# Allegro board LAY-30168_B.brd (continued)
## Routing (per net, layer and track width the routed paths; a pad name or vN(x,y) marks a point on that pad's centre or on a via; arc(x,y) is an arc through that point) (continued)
JTAG_MOD: length 13.2
  TOP w0.127: TP11.1 74.12,56.9 R303.1 72,56.52 71.88,56.39 66.22,56.39 65.96,56.13 63.44,56.13 63.21,55.9 62.31,55.9 U1.F13
JTAG_NSRST: length 9.5
  TOP w0.127: D13.C R175.2 28.07,88.27 28.21,88.41 28.21,94.01 J21.15
JTAG_RESET: length 16.2
  TOP w0.127: v2(131.61,77.37) 130,77.37 U38.D10 ; J44.2 136.78,84.45 v2(136.78,77.37)
  BOTTOM w0.127: v2(136.78,77.37) v2(131.61,77.37)
JTAG_RTCK: length 9
  TOP w0.127: R181.1 32.02,88.01 33.29,89.28 33.29,94.01 J21.11
JTAG_TCK: length 165.5
  TOP w0.127: v2(104.14,77.47) 104.14,75.44 104.9,74.68 104.9,58.34 102.97,56.4 86.43,56.4 85.02,57.81 66.19,57.81 65.28,56.9 63.37,56.9 63.01,56.54 61.66,56.54 U1.F12 ; J21.9 35.81,94.02 35.81,89.27 v2(34.56,88.01) R180.1
  BOTTOM w0.127: v2(104.14,77.47) 103.5,78.11 103.5,90.55 104.27,91.31 J48.2 102.23,92.33 90.81,92.33 89.41,93.73 52.4,93.73 47.7,89.03 40.26,89.03 38.61,87.38 35.19,87.38 v2(34.56,88.01)
JTAG_TDI_L: length 45.8
  TOP w0.127: U48.3 96.26,90.81 96.65,90.42 110.19,90.42 111.46,89.15 122.95,89.15 126.05,86.05 128.97,86.05 133.61,81.41 U38.J10
JTAG_TDI_TGTMCU_BUF: length 4.4
  TOP w0.127: R417.2 97.92,97.41 98.42,96.9 J49.1
JTAG_TDO_TGTMCU_BUF: length 11.2
  TOP w0.127: U49.4 93.97,88.03 93.34,88.65 92.72,88.65 R422.1 92.71,95.5 J50.1
JTAG_TMS: length 166.3
  TOP w0.127: R176.2 v2(37.1,88.01) 38.37,89.28 38.37,94.01 J21.7 ; v2(104.12,78.72) 103.63,78.23 103.63,75.18 104.52,74.3 104.52,58.49 102.81,56.78 86.59,56.78 85.13,58.24 65.89,58.24 64.86,57.22 62.99,57.22 U1.E14
  BOTTOM w0.127: v2(37.1,88.01) 38.5,89.41 47.54,89.41 52.37,94.23 89.53,94.23 90.93,92.84 100.84,92.84 103.5,95.5 106.81,95.5 J47.2 104.12,90.53 v2(104.12,78.72)
JTAG_VREF: length 8.9
  TOP w0.127: J21.1 45.97,94.02 45.97,88.62 R179.2
LCD_3V3: length 68
  TOP w0.305: v2(90.04,73.79) 90.04,72.14 89.15,71.25 88.14,71.25 87.66,71.73 85.57,71.73 84.79,72.52 81.86,72.52 79.46,74.92 v2(78.87,74.92) 76.6,74.92 70,68.33 v2(55.12,68.33)
  BOTTOM w0.305: J8.B1 C92.1
  BOTTOM w0.381: v2(55.12,68.33) 55.12,68.96 49.78,74.3 37.46,74.3 36.83,73.66 C92.1 ; R67.1 v2(78.87,74.92)
LCDIF_CLK: length 31
  TOP w0.127: v2(68.07,65.79) 68.07,66.55 68.58,67.06 74.17,67.06 76.83,69.72 78.49,69.72 v2(78.99,69.22) ; U1.D7 v1(57.77,57.84)
  BOTTOM w0.102: v1(57.77,57.84) 57.77,58.04 58.16,58.43 58.16,60.17
  BOTTOM w0.127: J8.A30 80.15,69.48 79.88,69.22 v2(78.99,69.22) ; v2(68.07,65.79) 67.58,65.29 62.71,65.29 58.16,60.75 58.16,60.17
LCDIF_D12: length 37.7
  TOP w0.127: U1.A11 60.7,60.2 60.9,60.4 60.9,60.52 63.25,62.87 78.52,62.87 80.28,64.63 89.3,64.63 89.92,65.25 89.92,68.76 v2(90.5,69.34)
  BOTTOM w0.127: J8.A9 90.65,69.49 v2(90.5,69.34)
LCDIF_D13: length 38.5
  TOP w0.127: v2(90.42,67.31) 90.42,65.12 89.56,64.26 80.44,64.26 78.67,62.5 63.39,62.5 61.03,60.14 61.03,59.15 U1.B11
  BOTTOM w0.127: J8.A10 90.15,69.83 90.03,69.71 90.03,67.7 v2(90.42,67.31)
LCDIF_D14: length 37.7
  TOP w0.127: U1.C11 v1(61.02,58.49)
  BOTTOM w0.102: v1(61.02,58.49) 61.02,58.7 61.5,59.18 63.12,59.18
  BOTTOM w0.127: J8.A11 89.65,64.5 88.14,62.99 85.47,62.99 83.79,61.32 65.25,61.32 63.12,59.18
LCDIF_D15: length 38.6
  TOP w0.127: U1.D11 v1(61.02,57.84)
  BOTTOM w0.102: 62.03,60.58 61.14,59.7 61.14,59.11 60.7,58.66 60.7,58.18 61.02,57.85 v1(61.02,57.84)
  BOTTOM w0.127: 62.03,60.58 63.09,61.65 83.42,61.65 85.07,63.3 87.93,63.3 89.15,64.51 J8.A12
LCDIF_ENABLE: length 28.7
  TOP w0.127: v2(69.22,65.79) 74.72,65.79 v2(78.15,69.22) ; U1.E7 v1(57.77,57.19)
  BOTTOM w0.102: v1(57.77,57.19) 58.09,57.52 58.09,58 58.42,58.33 58.42,60.46 58.54,60.58
  BOTTOM w0.127: 58.54,60.58 58.54,60.59 62.87,64.91 68.34,64.91 v2(69.22,65.79) ; J8.A34 v2(78.15,69.22)
LCDIF_HSYNC: length 32.5
  TOP w0.127: U1.E8 v1(59.07,57.19)
  BOTTOM w0.102: 58.96,60.58 58.75,60.36 58.75,57.52 v1(59.07,57.19)
  BOTTOM w0.127: J8.A32 79.15,71.6 78.49,72.26 73.15,72.26 70.61,69.72 70.61,66.29 68.83,64.52 62.9,64.52 58.96,60.58
LCDIF_VSYNC: length 30.8
  TOP w0.127: U1.D8 v1(59.07,57.84)
  BOTTOM w0.102: 59.39,60.58 58.99,60.17 58.99,57.93 v1(59.07,57.84)
  BOTTOM w0.127: 59.39,60.58 62.82,64.01 69.14,64.01 70.92,65.79 70.92,69.6 73.28,71.96 78.28,71.96 78.65,71.59 J8.A33
LDO_1V8: length 96.1
  BOTTOM w0.381: v2(49.02,9.91) v2(49.02,9.14) 53.37,4.8 69.62,4.8 71.12,3.3 75.69,3.3 78.87,6.48 90.55,6.48 91.31,5.71 93.22,5.71 102.36,14.86 116.33,14.86 126.11,5.08 L20.1
MAIN_MIC2N: length 3.2
  TOP w0.254: U13.5 127.38,29.09 C130.1 C126.2
MAIN_MIC2P: length 4.1
  TOP w0.254: U13.6 126.88,28.44 126.52,28.8 125.89,28.8 C118.2 124.34,29.47 C122.2
MCU_DCDC_IN: length 6.1
  TOP w0.254: U1.K4 v1(55.82,53.3) ; v1(52.83,52.6) 53.06,52.83 v1(53.31,52.83) 53.45,52.97 U1.L1 v1(54.52,52.64) U1.L2
  INT1 w0.102: 54.1,53.34 54.38,53.62 55.5,53.62 v1(55.82,53.3) 55.5,52.97 54.75,52.97
  vias: v2(43.43,46.99) v2(43.43,46.35)
MICBIAS: length 22.9
  TOP w0.254: U13.1 129.39,27.76 129.69,28.07 130.3,28.07
  TOP w0.305: R104.1 v2(127.89,34.92) ; v2(132.33,29.47) C112.1 131.57,29.34 130.3,28.07
  TOP w0.381: R105.1 v2(122.68,32.01)
  BOTTOM w0.305: v2(132.33,29.47) 128.9,29.47 127.89,30.48 v2(127.89,34.92) 123.11,34.92 122.68,34.49 v2(122.68,32.01)
NVCC_SD: length 15.2
  TOP w0.305: v2(48.64,50.16) 48.64,51.3 R60.1
  BOTTOM w0.305: v2(48.64,50.16) 46.02,47.55 42.85,47.55 40.51,45.21 v2(40.51,41.66)
ONOFF: length 69
  TOP w0.127: U1.M6 57.13,52 57.13,50.65 56.87,50.39 56.87,47.85 56.38,47.36 56.38,45.91 56.81,45.48 56.81,44.31 57.14,43.98 58.25,43.98 60.33,41.91 60.33,38.48 59.44,37.59 59.44,37.08 59.65,36.87 62.32,36.87 65.15,34.04 65.91,34.04 67.82,32.13 67.82,25.53 60.45,18.16 60.45,7.96 59.82,7.33 SW2.3 SW2.4
OTG1_DN: length 64.6
  TOP w0.102: v1(58.42,52.64) 58.74,52.32 U1.M8
  TOP w0.119: v2(61.14,46.49) 60.87,46.76 60.72,46.76 60.58,46.62 60.58,43.56 61.85,42.29 61.85,40.51 65.29,37.08 74.02,37.08 79.88,31.21 79.88,22.23 81.79,20.32 83.69,20.32 85.85,18.16 89.63,18.16 91.05,16.74 91.05,13.6 91.33,13.32 L5.2 R68.2
  BOTTOM w0.102: v1(58.42,52.64) 58.61,52.83 58.7,52.83 58.8,52.73 58.8,51.11 58.89,51.02 58.89,50.91 58.89,50.91 58.89,50.89
  BOTTOM w0.119: v2(61.14,46.49) 60.68,46.95 60.68,47.25 60.04,47.89 60.04,48.4 58.89,49.55 58.89,50.89
OTG1_DP: length 64.6
  TOP w0.102: v1(58.42,53.29) 58.74,52.97 U1.L8
  TOP w0.119: v2(61.14,47.34) 60.81,47.01 60.61,47.01 60.33,46.73 60.33,43.46 61.6,42.19 61.6,40.41 65.18,36.83 73.91,36.83 79.64,31.11 79.64,22.12 81.69,20.07 83.59,20.07 85.75,17.91 89.53,17.91 90.8,16.64 90.8,13.59 90.53,13.31 L5.3 R69.2
  BOTTOM w0.102: v1(58.42,53.29) 58.65,53.06 58.79,53.06 59.03,52.83 59.03,51.21 59.13,51.11 59.13,50.9
  BOTTOM w0.119: v2(61.14,47.34) 60.94,47.34 60.29,47.99 60.29,48.5 59.14,49.65 59.14,50.89 59.13,50.9
OTG2_DN: length 53.9
  TOP w0.102: 58.46,49.89 58.46,49.92 58.43,49.95 58.43,51.34 U1.N7
  TOP w0.119: 58.46,49.89 58.46,44.74 60.96,42.24 60.96,40.26 64.9,36.32 73.41,36.32 78.74,30.99 78.74,21.97 80.38,20.33 80.38,13.65 80.66,13.37 L8.2 R83.2
OTG2_DP: length 53.8
  TOP w0.102: 58.22,49.89 58.22,49.92 58.23,49.93 58.23,50.89 U1.P7
  TOP w0.119: R84.2 L8.3 79.86,13.36 80.13,13.63 80.13,13.94 80.01,14.06 79.93,14.06 79.81,14.18 79.81,14.42 79.93,14.53 80.01,14.53 80.13,14.65 80.13,14.89 80.01,15.01 79.93,15.01 79.81,15.13 79.81,15.37 79.93,15.49 80.01,15.49 80.13,15.61 80.13,20.23 78.49,21.87 78.49,30.89 73.3,36.08 64.79,36.08 60.71,40.16 60.71,42.14 58.22,44.63 58.22,49.89
PERI_3V3:
  vias: v2(89.92,75.69) v2(89.92,75.06) v2(90.68,75.69)
PERI_PWREN: length 121.2
  TOP w0.127: v2(91.82,79.76) 104.29,79.76 105.79,78.26 105.79,73.66 106.6,72.85 106.6,58.09 103.54,55.03 84.75,55.03 83.86,54.14 79.43,54.14 v2(78.74,53.45) ; U1.L7 v1(57.77,52.65) ; Q6.1 88.38,76.51 v2(88.77,76.91) R31.1
  BOTTOM w0.102: 58.09,50.9 58.09,52.32 v1(57.77,52.65)
  BOTTOM w0.127: v2(78.74,53.45) 78.74,52.7 77.34,51.31 76.71,51.31 75.31,49.91 75.31,37.08 73.03,34.8 71.12,34.8 69.85,36.07 69.85,39.37 68.58,40.64 65.56,40.64 60.34,45.86 60.34,47.16 58.45,49.05 58.45,50.55 58.09,50.9 ; v2(91.82,79.76) 91.62,79.76 v2(88.77,76.91)
PMIC_ON_REQ: length 65
  TOP w0.127: U1.K7 v1(57.77,53.3) ; v2(63.12,33.78) 62.48,33.15 50.8,33.15 v2(50.04,32.38) ; v2(44.32,17.27) 44.82,16.77 R355.1 ; v2(36.96,20.95) R38.2
  BOTTOM w0.102: v1(57.77,53.3) 57.77,53.1 57.44,52.78 57.44,50.24 57.61,50.07 57.61,49.91
  BOTTOM w0.127: v2(50.04,32.38) 50.04,29.84 44.96,24.77 44.96,17.91 v2(44.32,17.27) 43.69,17.91 38.73,17.91 36.96,19.68 v2(36.96,20.95) ; v2(63.12,33.78) 62.61,34.29 62.61,40.51 58.83,44.3 58.83,45.79 58.55,46.06 58.55,46.79 57.61,47.73 57.61,49.91
POR_B: length 242.6
  TOP w0.203: U44.7 143.26,87.25 R401.2 141.61,86.61 R410.2 139.96,86.48 138.68,87.76 134.75,87.76 J43.3
  TOP w0.254: U1.M7 v1(57.77,52)
  TOP w0.305: v2(32.64,43.18) D7.C 31.08,43.94 27.69,43.94 26.29,42.55 J26.1 25.4,70.1 22.1,73.41 22.1,82.42 25.44,85.76 D13.A v2(27.85,85.76) ; J43.3 129.93,89.53 D21.C 128.74,90.22 124.16,90.22 123.8,90.58 114.4,90.58 114.05,90.93 113.16,90.93 v2(113.03,91.06) ; R20.2 C27.1 61.62,43.18 v2(61.11,43.69) ; v2(63.12,34.67) v2(47.75,34.67)
  BOTTOM w0.254: v1(57.77,52) 57.77,50.48 58.04,50.22 58.04,47.85
  BOTTOM w0.305: 58.04,47.85 59.06,46.83 R21.2 59.06,46.11 59.24,45.93 59.24,44.65 59.87,44.02 60.78,44.02 v2(61.11,43.69) 63.12,41.68 v2(63.12,34.67) ; v2(47.75,34.67) 46.56,35.86 44.91,35.86 37.59,43.18 v2(32.64,43.18) ; v2(27.85,85.76) 32.26,90.17 46.91,90.17 51.59,94.84 85.45,94.84 88.77,98.17 109.6,98.17 113.03,94.74 v2(113.03,91.06)
POR_BUTTON: length 20.4
  TOP w0.127: R355.2 R43.1 43.3,15.63 44.32,14.6 44.32,8.13 43.52,7.33 SW3.3 SW3.4
POWER_EN: length 16.8
  TOP w0.305: U38.F7 v2(131.61,75.77) ; R216.1 v2(126.49,63.25)
  BOTTOM w0.305: v2(131.61,75.77) 132.72,74.66 132.72,70.1 126.49,63.88 v2(126.49,63.25)
PWDN: length 7.5
  TOP w0.254: J35.17 134.96,8.85 135.64,9.53 136.02,9.53 136.4,9.91 R219.2 136.14,10.55 135.83,10.86 D17.A
SD0_VSELECT: length 120.6
  TOP w0.254: U1.C14 63.89,58.17 65.05,59.33 v2(85.09,59.33) ; Q9.2 41.38,37.1 41.18,37.29 41.18,37.83 41.45,38.1 R54.1 42.55,36.32 43.43,35.43 63.11,35.43 65.4,33.15 65.96,33.15 67.18,31.93 v2(67.18,29.21) ; v2(96.14,32) v2(85.34,32)
  BOTTOM w0.254: v2(85.09,59.33) 85.09,58.8 86.61,57.28 89.11,57.28 96.9,49.48 96.9,32.77 v2(96.14,32) ; v2(85.34,32) 82.68,32 79.88,29.21 v2(67.18,29.21)
SD1_CLK: length 19.1
  TOP w0.127: U1.J3 v1(55.17,53.95)
  BOTTOM w0.102: v1(55.17,53.95) 54.64,53.95 54.61,53.98 53.09,53.98 52.32,53.21
  BOTTOM w0.127: R282.1 39.74,48.39 C244.1 41.52,48.38 42.1,48.96 45.48,48.96 48.76,52.25 49.58,52.25 50.16,52.83 51.27,52.83 51.66,53.21 52.32,53.21
SD1_D2: length 54.1
  TOP w0.127: TP27.1 49.4,53.09 v2(49.4,53.34) 49.78,53.34 50.67,54.23 53.38,54.23 53.76,54.6 54.53,54.6 U1.H2 ; v2(19.94,51.69) 19.03,50.78 J39.1
  BOTTOM w0.127: v2(49.4,53.34) 48.92,52.86 48.46,52.86 45.17,49.57 41.53,49.57 41.36,49.4 28.02,49.4 26.37,51.05 25.28,51.05 25.15,51.18 25.15,51.56 25.03,51.69 24.77,51.69 24.65,51.56 24.65,51.18 24.52,51.05 24.18,51.05 24.06,51.18 24.06,52.2 23.93,52.32 23.68,52.32 23.55,52.2 23.55,51.18 23.42,51.05 23.17,51.05 23.04,51.18 23.04,52.2 22.91,52.32 22.66,52.32 22.53,52.2 22.53,51.18 22.41,51.05 22.15,51.05 22.02,51.18 22.02,52.2 21.9,52.32 21.64,52.32 21.52,52.2 21.52,51.82 21.39,51.69 v2(19.94,51.69)
SD1_D3: length 54.8
  TOP w0.127: U1.J2 54.52,53.95 53.89,53.95 53.55,53.61 52.21,53.61 51.94,53.34 v2(51.05,53.34) 50.87,53.15 50.87,51.63 TP28.1 ; v2(17.65,52.7) 16.83,51.88 J39.2
  BOTTOM w0.127: v2(17.65,52.7) R172.1 18.42,52.06 19.56,50.93 21.08,50.93 22.1,49.91 22.1,49.52 22.23,49.39 22.48,49.39 22.61,49.52 22.61,50.29 22.74,50.42 22.99,50.42 23.12,50.29 23.12,49.52 23.25,49.39 23.5,49.39 23.63,49.52 23.63,50.24 23.75,50.37 24.01,50.37 24.13,50.24 24.13,49.52 24.26,49.39 24.52,49.39 24.64,49.52 24.64,50.19 24.77,50.32 25.02,50.32 25.15,50.19 25.15,49.52 25.28,49.39 25.53,49.39 25.66,49.52 25.66,50.06 25.79,50.19 26.14,50.19 27.36,48.97 41.49,48.97 41.78,49.26 45.32,49.26 48.61,52.55 49.38,52.55 50.17,53.34 51.05,53.34 v2(51.05,53.34)
SD_CD_SW: length 151.7
  TOP w0.127: v2(27.94,57.78) 27.94,63.25 31.88,67.18 52.95,67.18 54.61,68.85 68.59,68.85 77.69,77.94 99.81,77.94 103.89,73.86 103.89,58.72 102.56,57.39 86.84,57.39 85.38,58.85 65.46,58.85 64.44,57.84 62.51,57.84 62.2,57.52 U1.D13
  BOTTOM w0.127: R320.2 24.5,57.78 24.51,57.78 v2(27.94,57.78)
SDA_JTAG_TCLK: length 24.2
  TOP w0.127: U38.H2 133.2,71.76 133.2,74.74 132.99,74.96 131.03,74.96 130.81,75.18 130.81,76.43 130.68,76.56 129.41,76.56 129.2,76.77 129.2,77.13 128.97,77.36 128.61,77.36 128.4,77.57 128.4,77.93 126.32,80.01 124.59,80.01 123.19,81.41 121.92,81.41 120.27,83.06 120.27,83.69 J34.4
SDA_JTAG_TDI: length 20.6
  TOP w0.127: J34.8 121.79,79.63 121.79,77.22 122.3,76.71 124.59,76.71 125.73,75.56 126.75,75.56 126.96,75.77 127.43,75.77 127.62,75.58 127.62,75.2 127.85,74.97 128.96,74.97 129.2,74.73 129.2,74.42 129.45,74.17 130.68,74.17 130.82,74.03 130.82,73.6 131.05,73.37 131.48,73.37 131.6,73.25 131.6,72.57 U38.G3
SDA_JTAG_TDO: length 21.9
  TOP w0.127: U38.H3 132.42,72.56 132.42,73.92 132.16,74.17 131.05,74.17 130.82,74.4 130.82,74.72 130.56,74.97 130.23,74.97 130.02,75.19 130.02,75.55 129.79,75.77 127.85,75.77 127.6,76.02 127.6,76.33 127.37,76.56 126.51,76.56 125.35,77.72 122.81,77.72 122.17,78.36 122.17,80.52 J34.6
SDA_JTAG_TMS: length 24.1
  TOP w0.127: J34.2 120.91,84.32 R213.2 v2(120.91,83.19) ; U38.C4 128.4,72.56 125.65,72.56 124.46,71.37 122.3,71.37 121.92,71.75 121.92,73.41 120.9,74.42 v2(120.9,78.36)
  BOTTOM w0.127: v2(120.91,83.19) 120.9,83.18 v2(120.9,78.36)
SDA_RST: length 16
  TOP w0.127: U38.B4 127.61,73.37 124.42,73.37 R423.2 123.39,73.46 122.5,73.46 121.41,74.55 121.41,78.74 J34.10
SDA_RST_LED: length 1.6
  TOP w0.127: R412.2 128.13,88.28 D21.A
SDA_RST_TGTMCU_J_B: length 15.1
  TOP w0.127: J44.1 141.47,85.72 R410.1 142.25,84.96 145.92,84.96 147.32,86.36 147.32,90.04 R400.1
SDA_USB_CONN_DM: length 11.7
  TOP w0.119: J41.2 145.32,72.24 145.13,72.42 144.78,72.42 U39.2 143.86,72.26 143.74,72.38 143.47,72.38 143.25,72.16 143.25,70.86 140.62,68.23 138.35,68.23 R375.1
SDA_USB_CONN_DP: length 11.7
  TOP w0.119: R376.1 138.35,68.47 140.52,68.47 143,70.96 143,72.26 143.37,72.63 143.74,72.63 143.86,72.75 U39.3 144.68,72.69 145.16,72.69 145.35,72.89 J41.3
SDA_USB_DM: length 9.7
  TOP w0.119: U38.E2 130.41,71.23 130.02,70.84 130.02,69.91 131.7,68.23 136.96,68.23 R375.2
SDA_USB_DP: length 8.4
  TOP w0.119: R376.2 136.96,68.47 131.81,68.47 130.27,70.01 130.27,70.45 130.39,70.57 U38.E1
SDRAM_3V3: length 12.2
  TOP w0.254: U20.B3 v2(36.45,58.99) 36.51,58.93 37.72,58.93 ; U20.J9 v2(30.06,54.19) ; U20.E7 v2(34.06,55.79) ; U20.A9 37.25,54.19 37.93,54.19 38.1,54.36 C169.1 ; U20.A7 v2(37.25,56.59) 37.71,56.13 C167.1 ; U20.D3 v2(34.85,59.78) ; U20.C7 v2(35.65,56.59)
  TOP w0.305: C165.1 38.1,59.31 37.72,58.93 ; C169.1 C167.1
SEMC_A0: length 34.4
  TOP w0.127: U1.C2 54.53,58.49 53.21,58.49 52.14,59.56 45.12,59.56 44.97,59.41 44.97,58.7 44.82,58.55 44.61,58.55 44.46,58.7 44.46,59.41 44.31,59.56 44.1,59.56 43.95,59.41 43.95,58.7 43.8,58.55 43.59,58.55 43.44,58.7 43.44,59.41 43.3,59.56 43.09,59.56 42.94,59.41 42.94,58.7 42.79,58.55 42.58,58.55 42.43,58.7 42.43,59.41 42.28,59.56 42.07,59.56 41.92,59.41 41.92,58.7 41.77,58.55 41.56,58.55 41.41,58.7 41.41,59.41 41.26,59.56 41.02,59.56 40.89,59.44 40.89,58.04 40.26,57.4 30.99,57.4 30.73,57.15 30.73,56.71 U20.H7
SEMC_A1: length 34.6
  TOP w0.127: U20.H8 30.86,54.99 30.86,54.02 30.73,53.89 30.53,53.89 30.4,53.77 30.4,53.51 30.53,53.38 30.73,53.38 30.86,53.26 30.86,52.76 30.07,51.97 30.07,51.56 31.06,50.58 31.24,50.58 31.5,50.84 31.68,50.84 31.86,50.66 31.86,50.48 31.6,50.22 31.6,50.04 31.78,49.86 31.96,49.86 32.22,50.12 32.4,50.12 32.58,49.95 32.58,49.77 32.31,49.5 32.31,49.32 32.49,49.15 42.39,49.15 48.55,55.31 52.79,55.31 53.06,55.57 U1.G1
SEMC_A2: length 34.7
  TOP w0.127: U20.J8 29.64,54.57 29.64,53.34 29.77,53.21 29.97,53.21 30.1,53.08 30.1,52.83 29.97,52.7 29.77,52.7 29.64,52.57 29.64,51.36 32.23,48.77 42.49,48.77 48.65,54.93 52.95,54.93 53.26,55.24 55.17,55.24 U1.G3
SEMC_A3: length 34.3
  TOP w0.127: U20.J7 29.31,55.04 29.31,50.98 31.9,48.39 42.62,48.39 48.78,54.55 53.21,54.55 53.58,54.92 U1.H1
SEMC_A4: length 36.7
  TOP w0.127: U20.J3 29.34,60.5 29.34,62.61 32.51,65.79 52.83,65.79 57.44,61.17 U1.A6
SEMC_A5: length 35.3
  TOP w0.127: U1.B6 57.13,59.14 57.13,60.86 52.58,65.41 32.64,65.41 29.67,62.43 29.67,60.97 U20.J2
SEMC_A6: length 34.8
  TOP w0.127: U1.B1 53.32,58.82 52.96,59.18 52.96,59.82 52.83,59.94 52.61,59.94 52.46,60.09 52.46,60.56 52.31,60.71 52.1,60.71 51.96,60.56 51.96,60.09 51.81,59.94 51.6,59.94 51.45,60.09 51.45,60.56 51.3,60.71 51.09,60.71 50.94,60.56 50.94,60.09 50.79,59.94 50.58,59.94 50.43,60.09 50.43,60.56 50.28,60.71 50.07,60.71 49.92,60.56 49.92,60.09 49.77,59.94 49.56,59.94 49.42,60.09 49.42,60.56 49.27,60.71 49.06,60.71 48.91,60.56 48.91,60.09 48.76,59.94 48.55,59.94 48.4,60.09 48.4,60.56 48.25,60.71 48.04,60.71 47.89,60.56 47.89,60.09 47.74,59.94 40.77,59.94 40.51,59.69 40.51,58.8 39.5,57.78 31.89,57.78 31.74,57.93 31.74,58.4 31.59,58.55 31.38,58.55 31.23,58.4 31.23,57.93 31.08,57.78 30.73,57.78 30.48,58.04 30.48,58.61 U20.H3
SEMC_A7: length 34.9
  TOP w0.127: U20.H2 30.86,60.58 30.86,63.12 32.77,65.02 44.95,65.02 45.1,64.88 45.1,64.79 45.24,64.64 45.45,64.64 45.6,64.79 45.6,64.88 45.75,65.02 45.96,65.02 46.11,64.88 46.11,64.79 46.26,64.64 46.47,64.64 46.62,64.79 46.62,64.88 46.77,65.02 46.98,65.02 47.13,64.88 47.13,64.79 47.28,64.64 47.49,64.64 47.64,64.79 47.64,64.88 47.78,65.02 47.99,65.02 48.14,64.88 48.14,64.79 48.29,64.64 48.5,64.64 48.65,64.79 48.65,64.88 48.8,65.02 49.01,65.02 49.16,64.88 49.16,64.79 49.31,64.64 49.52,64.64 49.67,64.79 49.67,64.88 49.82,65.02 52.46,65.02 56.79,60.69 U1.A5
SEMC_A8: length 34.8
  TOP w0.127: U20.H1 31.25,63 32.51,64.26 33.39,64.26 33.54,64.41 33.54,64.49 33.69,64.64 33.9,64.64 34.05,64.49 34.05,64.41 34.2,64.26 34.41,64.26 34.56,64.41 34.56,64.49 34.7,64.64 34.92,64.64 35.06,64.49 35.06,64.41 35.21,64.26 35.42,64.26 35.57,64.41 35.57,64.49 35.72,64.64 35.93,64.64 36.08,64.49 36.08,64.41 36.23,64.26 36.44,64.26 36.59,64.41 36.59,64.49 36.74,64.64 36.95,64.64 37.1,64.49 37.1,64.41 37.24,64.26 37.46,64.26 37.6,64.41 37.6,64.49 37.75,64.64 37.96,64.64 38.11,64.49 38.11,64.41 38.26,64.26 38.47,64.26 38.62,64.41 38.62,64.49 38.77,64.64 38.98,64.64 39.13,64.49 39.13,64.41 39.28,64.26 39.49,64.26 39.64,64.41 39.64,64.49 39.78,64.64 40,64.64 40.14,64.49 40.14,64.41 40.29,64.26 40.5,64.26 40.65,64.41 40.65,64.49 40.8,64.64 41.01,64.64 41.16,64.49 41.16,64.41 41.31,64.26 41.52,64.26 41.67,64.41 41.67,64.49 41.82,64.64 42.03,64.64 42.18,64.49 42.18,64.41 42.32,64.26 42.54,64.26 42.68,64.41 42.68,64.49 42.83,64.64 43.04,64.64 43.19,64.49 43.19,64.41 43.34,64.26 43.55,64.26 43.7,64.41 43.7,64.49 43.85,64.64 44.06,64.64 44.21,64.49 44.21,64.41 44.36,64.26 52.7,64.26 56.14,60.82 U1.A4
SEMC_A9: length 35.3
  TOP w0.127: U20.G3 33.27,58.17 39.37,58.17 40.13,58.93 40.13,60.71 40.51,61.09 40.7,61.09 40.85,60.94 40.85,60.47 41,60.33 41.21,60.33 41.36,60.47 41.36,60.94 41.5,61.09 41.71,61.09 41.86,60.94 41.86,60.47 42.01,60.33 42.22,60.33 42.37,60.47 42.37,60.94 42.52,61.09 42.73,61.09 42.88,60.94 42.88,60.47 43.03,60.33 43.24,60.33 43.39,60.47 43.39,60.94 43.54,61.09 43.75,61.09 43.9,60.94 43.9,60.47 44.04,60.33 44.25,60.33 44.4,60.47 44.4,60.94 44.55,61.09 44.76,61.09 44.91,60.94 44.91,60.47 45.06,60.33 45.27,60.33 45.42,60.47 45.42,60.94 45.57,61.09 45.78,61.09 45.93,60.94 45.93,60.47 46.08,60.33 46.29,60.33 46.44,60.47 46.44,60.94 46.58,61.09 46.79,61.09 46.94,60.94 46.94,60.47 47.09,60.33 47.3,60.33 47.45,60.47 47.45,60.94 47.6,61.09 52.7,61.09 53.34,60.45 53.34,59.39 53.59,59.14 54.33,59.14 54.65,58.82 U1.B2
SEMC_A10: length 35
  TOP w0.127: U20.H9 31.25,52.51 31.42,52.35 31.42,52.17 30.84,51.59 30.84,51.41 31.02,51.23 31.2,51.23 31.78,51.81 31.96,51.81 32.37,51.4 32.37,51.22 32.17,51.02 32.17,50.84 32.35,50.66 32.53,50.66 32.73,50.86 32.91,50.86 33.38,50.39 33.38,50.21 33.05,49.89 33.05,49.71 33.23,49.53 33.41,49.53 33.74,49.85 33.92,49.85 34.32,49.45 39.17,49.45 39.38,49.67 39.38,49.96 39.51,50.09 39.76,50.09 39.89,49.96 39.89,49.66 40.02,49.53 40.27,49.53 40.4,49.66 40.4,49.96 40.52,50.09 40.78,50.09 40.9,49.96 40.9,49.77 41.1,49.58 42.29,49.58 48.46,55.75 52.74,55.75 52.88,55.89 54.53,55.89 U1.G2
SEMC_A11: length 34.8
  TOP w0.127: U20.G2 31.62,60.62 31.62,60.83 31.62,62.87 32.64,63.88 46.28,63.88 46.43,63.73 46.43,63.52 46.58,63.37 46.79,63.37 46.94,63.52 46.94,63.73 47.09,63.88 47.48,63.88 47.63,63.73 47.63,63.52 47.78,63.37 47.99,63.37 48.13,63.52 48.13,63.73 48.28,63.88 48.49,63.88 48.64,63.73 48.64,63.52 48.79,63.37 49,63.37 49.15,63.52 49.15,63.73 49.3,63.88 49.51,63.88 49.66,63.73 49.66,63.52 49.81,63.37 50.02,63.37 50.17,63.52 50.17,63.73 50.32,63.88 50.53,63.88 50.67,63.73 50.67,63.52 50.82,63.37 51.03,63.37 51.18,63.52 51.18,63.73 51.33,63.88 51.54,63.88 51.69,63.73 51.69,63.52 51.84,63.37 52.05,63.37 52.2,63.52 52.2,63.73 52.35,63.88 52.58,63.88 55.81,60.65 55.81,59.15 U1.B4
SEMC_A12: length 34.3
  TOP w0.127: U1.A3 55.49,60.33 52.83,62.99 46.26,62.99 46.11,63.14 46.11,63.35 45.96,63.5 45.75,63.5 45.6,63.35 45.6,63.14 45.45,62.99 45.24,62.99 45.09,63.14 45.09,63.35 44.94,63.5 44.73,63.5 44.58,63.35 44.58,63.14 44.43,62.99 44.22,62.99 44.08,63.14 44.08,63.35 43.93,63.5 43.72,63.5 43.57,63.35 43.57,63.14 43.42,62.99 43.21,62.99 43.06,63.14 43.06,63.35 42.91,63.5 42.7,63.5 42.55,63.35 42.55,63.14 42.4,62.99 42.19,62.99 42.04,63.14 42.04,63.35 41.89,63.5 41.39,63.5 41.14,63.25 40.88,63.25 40.63,63.5 39.78,63.5 39.63,63.35 39.63,63.14 39.48,62.99 39.27,62.99 39.12,63.14 39.12,63.35 38.97,63.5 38.76,63.5 38.61,63.35 38.61,63.14 38.47,62.99 38.26,62.99 38.11,63.14 38.11,63.35 37.96,63.5 37.75,63.5 37.6,63.35 37.6,63.14 37.45,62.99 37.24,62.99 37.09,63.14 37.09,63.35 36.94,63.5 36.73,63.5 36.58,63.35 36.58,63.14 36.43,62.99 36.22,62.99 36.07,63.14 36.07,63.35 35.93,63.5 35.72,63.5 35.57,63.35 35.57,63.14 35.42,62.99 35.21,62.99 35.06,63.14 35.06,63.35 34.91,63.5 34.7,63.5 34.55,63.35 34.55,63.14 34.4,62.99 34.19,62.99 34.04,63.14 34.04,63.35 33.89,63.5 33.4,63.5 32.06,62.15 U20.G1
SEMC_BA0: length 35.1
  TOP w0.127: U20.G7 32.06,56.9 32.18,57.02 40.39,57.02 41.53,58.17 45.22,58.17 45.37,58.32 45.37,59.03 45.52,59.18 45.73,59.18 45.88,59.03 45.88,58.32 46.02,58.17 46.34,58.17 46.49,58.32 46.49,59.03 46.64,59.18 46.85,59.18 47,59.03 47,58.32 47.15,58.17 47.36,58.17 47.51,58.32 47.51,59.03 47.66,59.18 47.87,59.18 48.02,59.03 48.02,58.32 48.17,58.17 48.38,58.17 48.53,58.32 48.53,59.03 48.67,59.18 48.88,59.18 49.03,59.03 49.03,58.32 49.18,58.17 49.39,58.17 49.54,58.32 49.54,59.03 49.69,59.18 49.9,59.18 50.05,59.03 50.05,58.32 50.2,58.17 50.41,58.17 50.56,58.32 50.56,59.03 50.71,59.18 50.92,59.18 51.07,59.03 51.07,58.32 51.21,58.17 51.42,58.17 51.57,58.32 51.57,59.03 51.72,59.18 51.93,59.18 52.08,59.03 52.08,58.32 52.23,58.17 U1.C1
SEMC_BA1: length 35.5
  TOP w0.127: U20.G8 31.69,55.02 31.69,52.64 34.29,50.04 34.65,50.04 34.8,50.19 34.8,50.27 34.95,50.42 36.43,50.42 36.58,50.27 36.58,50.06 36.73,49.91 36.94,49.91 37.09,50.06 37.09,50.27 37.23,50.42 38.21,50.42 38.36,50.27 38.36,50.06 38.5,49.91 38.71,49.91 38.86,50.06 38.86,50.27 39.01,50.42 40.89,50.42 41.38,50.91 42.48,50.91 42.65,50.74 42.86,50.74 43.01,50.88 43.01,51.09 42.84,51.27 42.84,51.48 42.99,51.62 43.2,51.62 43.37,51.45 43.58,51.45 43.73,51.6 43.73,51.81 43.56,51.98 43.56,52.19 43.71,52.34 43.92,52.34 44.09,52.17 44.3,52.17 44.45,52.32 44.45,52.53 44.28,52.7 44.28,52.91 44.43,53.06 44.64,53.06 44.81,52.89 45.02,52.89 45.17,53.04 45.17,53.25 45,53.42 45,53.63 45.14,53.78 45.36,53.78 45.53,53.61 45.74,53.61 45.89,53.76 45.89,53.97 45.71,54.14 45.71,54.35 45.86,54.5 46.07,54.5 46.24,54.33 46.45,54.33 46.6,54.48 46.6,54.69 46.43,54.86 46.43,55.07 46.58,55.22 46.79,55.22 46.96,55.05 47.17,55.05 47.32,55.2 47.32,55.41 47.15,55.58 47.15,55.79 47.42,56.06 52.32,56.06 52.49,56.22 U1.F1
SEMC_CAS: length 34.4
  TOP w0.127: U20.F7 33.27,55.77 33.27,53.98 34.04,53.21 39.75,53.21 41.02,54.48 41.02,54.69 40.6,55.12 40.6,55.33 40.75,55.48 40.96,55.48 41.38,55.05 41.59,55.05 41.82,55.28 41.82,55.49 41.14,56.17 41.14,56.38 41.29,56.53 41.5,56.53 42.18,55.85 42.39,55.85 42.54,56 42.54,56.21 41.86,56.89 41.86,57.1 42.01,57.25 42.22,57.25 42.9,56.57 43.11,56.57 43.28,56.74 43.28,56.95 42.79,57.44 42.79,57.65 42.94,57.79 43.15,57.79 43.63,57.31 43.84,57.31 44.2,57.66 53.27,57.66 53.47,57.85 55.16,57.85 U1.D3
SEMC_CKE: length 35.1
  TOP w0.127: U20.F3 33.69,58.55 39.12,58.55 39.62,59.05 R185.1 40.01,61.34 40.13,61.47 42.63,61.47 42.77,61.62 42.77,61.95 42.92,62.1 43.13,62.1 43.28,61.95 43.28,61.62 43.43,61.47 43.64,61.47 43.79,61.62 43.79,61.95 43.94,62.1 44.15,62.1 44.3,61.95 44.3,61.62 44.45,61.47 44.66,61.47 44.81,61.62 44.81,61.95 44.96,62.1 45.17,62.1 45.31,61.95 45.31,61.62 45.46,61.47 45.67,61.47 45.82,61.62 45.82,61.95 45.97,62.1 46.18,62.1 46.33,61.95 46.33,61.62 46.48,61.47 46.69,61.47 46.84,61.62 46.84,61.95 46.99,62.1 47.2,62.1 47.35,61.95 47.35,61.62 47.5,61.47 47.71,61.47 47.85,61.62 47.85,61.95 48,62.1 48.21,62.1 48.36,61.95 48.36,61.62 48.51,61.47 48.72,61.47 48.87,61.62 48.87,61.95 49.02,62.1 49.23,62.1 49.38,61.95 49.38,61.62 49.53,61.47 49.74,61.47 49.89,61.62 49.89,61.95 50.04,62.1 50.25,62.1 50.39,61.95 50.39,61.62 50.54,61.47 50.75,61.47 50.9,61.62 50.9,61.95 51.05,62.1 51.26,62.1 51.41,61.95 51.41,61.62 51.56,61.47 51.77,61.47 51.92,61.62 51.92,61.95 52.07,62.1 52.28,62.1 52.43,61.95 52.43,61.62 52.58,61.47 53.09,61.47 54.84,59.71 U1.A2
SEMC_CLK: length 16
  TOP w0.127: U1.B3 55.16,59.15 55.16,60.03 52.58,62.61 42.42,62.61 42.16,62.36 R283.1
SEMC_CS0: length 35.9
  TOP w0.127: U20.G9 32.06,53.54 v2(32.26,53.34) 32.26,52.7 34.16,50.8 34.56,50.8 34.71,50.95 34.71,51.16 34.86,51.31 35.07,51.31 35.22,51.16 35.22,50.95 35.37,50.8 35.58,50.8 35.73,50.95 35.73,51.16 35.88,51.31 36.09,51.31 36.24,51.16 36.24,50.95 36.39,50.8 36.6,50.8 36.74,50.95 36.74,51.16 36.89,51.31 37.1,51.31 37.25,51.16 37.25,50.95 37.4,50.8 37.61,50.8 37.76,50.95 37.76,51.16 37.91,51.31 38.12,51.31 38.27,51.16 38.27,50.95 38.42,50.8 38.63,50.8 38.78,50.95 38.78,51.16 38.93,51.31 39.14,51.31 39.28,51.16 39.28,50.95 39.43,50.8 39.64,50.8 39.79,50.95 39.79,51.16 39.94,51.31 40.15,51.31 40.3,51.16 40.3,50.95 40.45,50.8 40.77,50.8 41.43,51.46 41.76,51.46 41.87,51.35 42.08,51.35 42.23,51.5 42.23,51.71 42.12,51.82 42.12,52.03 42.27,52.18 42.48,52.18 42.59,52.07 42.8,52.07 42.95,52.22 42.95,52.43 42.84,52.54 42.84,52.75 42.99,52.9 43.2,52.9 43.31,52.79 43.52,52.79 43.67,52.94 43.67,53.15 43.56,53.26 43.56,53.47 43.71,53.62 43.92,53.62 44.03,53.51 44.24,53.51 44.39,53.66 44.39,53.87 44.28,53.98 44.28,54.19 44.43,54.33 44.64,54.33 44.75,54.23 44.96,54.23 45.11,54.38 45.11,54.59 45,54.69 45,54.9 45.15,55.05 45.36,55.05 45.47,54.95 45.68,54.95 45.82,55.1 45.82,55.31 45.72,55.41 45.72,55.62 45.87,55.77 46.08,55.77 46.18,55.67 46.39,55.67 46.54,55.81 46.54,56.02 46.44,56.13 46.44,56.34 46.61,56.52 53.84,56.52 U1.E1
  BOTTOM w0.127: R184.2 32.06,53.54 v2(32.26,53.34)
SEMC_D0: length 34.6
  TOP w0.127: U20.A8 v2(37.25,54.99) ; U1.E3 v1(55.17,57.19)
  BOTTOM w0.127: v2(37.25,54.99) 37.72,55.45 37.72,58.55 37.97,58.8 38.17,58.8 38.31,58.95 38.31,59.8 38.46,59.94 38.67,59.94 38.82,59.8 38.82,58.95 38.97,58.8 39.18,58.8 39.33,58.95 39.33,59.8 39.48,59.94 39.69,59.94 39.84,59.8 39.84,58.95 39.99,58.8 40.2,58.8 40.35,58.95 40.35,59.8 40.49,59.94 40.71,59.94 40.85,59.8 40.85,58.95 41,58.8 41.21,58.8 41.36,58.95 41.36,59.8 41.51,59.94 41.72,59.94 41.87,59.8 41.87,58.95 42.02,58.8 42.23,58.8 42.38,58.95 42.38,59.8 42.53,59.94 42.74,59.94 42.89,59.8 42.89,58.95 43.03,58.8 43.25,58.8 43.39,58.95 43.39,59.8 43.54,59.94 43.75,59.94 43.9,59.8 43.9,58.95 44.05,58.8 51.69,58.8 52.58,57.91 53.85,57.91 54.57,57.19 v1(55.17,57.19)
SEMC_D1: length 34.5
  TOP w0.127: U1.F3 v1(55.17,56.54) ; U20.B9 v2(36.45,54.19)
  BOTTOM w0.102: v1(55.17,56.54) 54.98,56.54 54.65,56.22 54.1,56.22 53.17,57.15
  BOTTOM w0.127: 53.17,57.15 44.72,57.15 44.57,57.3 44.57,57.89 44.42,58.04 44.21,58.04 44.06,57.89 44.06,57.3 43.91,57.15 43.7,57.15 43.55,57.3 43.55,57.89 43.41,58.04 43.2,58.04 43.05,57.89 43.05,57.3 42.9,57.15 42.69,57.15 42.54,57.3 42.54,57.89 42.39,58.04 42.18,58.04 42.03,57.89 42.03,57.3 41.88,57.15 41.67,57.15 41.52,57.3 41.52,57.89 41.37,58.04 41.16,58.04 41.01,57.89 41.01,57.3 40.87,57.15 40.66,57.15 40.51,57.3 40.51,57.89 40.36,58.04 40.15,58.04 40,57.89 40,57.3 39.85,57.15 39.64,57.15 39.49,57.3 39.49,57.89 39.34,58.04 39.13,58.04 38.98,57.89 38.98,57.3 38.83,57.15 38.61,57.15 38.48,57.02 38.48,56.71 38.63,56.56 39.48,56.56 39.62,56.42 39.62,56.21 39.48,56.06 38.63,56.06 38.48,55.91 38.48,55.71 38.63,55.56 38.84,55.56 38.99,55.41 38.99,55.2 38.84,55.05 38.63,55.05 38.48,54.9 38.48,54.61 37.59,53.72 36.92,53.72 v2(36.45,54.19)
SEMC_D2: length 34.3
  TOP w0.127: U1.F4 v1(55.82,56.54) ; U20.B8 v2(36.45,54.99)
  BOTTOM w0.102: 54.23,56.87 55.49,56.87 v1(55.82,56.54)
  BOTTOM w0.127: 54.23,56.87 53.57,57.53 52.27,57.53 52.12,57.68 52.12,57.89 51.97,58.04 51.76,58.04 51.61,57.89 51.61,57.68 51.46,57.53 51.23,57.53 51.08,57.68 51.08,58.27 50.93,58.42 50.72,58.42 50.58,58.27 50.58,57.68 50.43,57.53 50.24,57.53 50.09,57.68 50.09,58.27 49.94,58.42 49.73,58.42 49.58,58.27 49.58,57.68 49.43,57.53 49.22,57.53 49.07,57.68 49.07,58.27 48.92,58.42 48.71,58.42 48.56,58.27 48.56,57.68 48.42,57.53 48.21,57.53 48.06,57.68 48.06,58.27 47.91,58.42 47.7,58.42 47.55,58.27 47.55,57.68 47.4,57.53 47.19,57.53 47.04,57.68 47.04,58.27 46.89,58.42 46.68,58.42 46.53,58.27 46.53,57.68 46.38,57.53 46.17,57.53 46.02,57.68 46.02,58.27 45.88,58.42 45.67,58.42 45.52,58.27 45.52,57.68 45.37,57.53 45.16,57.53 45.01,57.68 45.01,58.27 44.86,58.42 38.48,58.42 38.1,58.04 38.1,54.99 37.71,54.6 36.84,54.6 v2(36.45,54.99)
SEMC_D3: length 34.5
  TOP w0.127: U20.C9 v2(35.65,54.19) ; U1.G4 v1(55.82,55.89)
  BOTTOM w0.102: v1(55.82,55.89) 55.5,56.22 55.04,56.22 54.78,55.97 53.89,55.97 53.09,56.77
  BOTTOM w0.127: v2(35.65,54.19) 36.54,53.3 37.68,53.3 38.48,54.1 38.67,54.1 38.81,54.25 38.81,54.46 38.96,54.61 39.17,54.61 39.32,54.46 39.32,54.25 39.47,54.1 40.01,54.1 40.13,54.23 40.13,54.46 40.28,54.61 40.87,54.61 41.02,54.75 41.02,54.96 40.87,55.11 40.28,55.11 40.13,55.26 40.13,55.47 40.28,55.62 40.75,55.62 40.89,55.77 40.89,55.98 40.75,56.13 40.28,56.13 40.13,56.28 40.13,56.52 40.39,56.77 41.35,56.77 41.5,56.62 41.5,55.39 41.64,55.24 41.86,55.24 42,55.39 42,56.62 42.15,56.77 42.36,56.77 42.51,56.62 42.51,55.65 42.66,55.5 42.87,55.5 43.02,55.65 43.02,56.62 43.17,56.77 43.93,56.77 44.08,56.62 44.08,56.03 44.23,55.88 44.44,55.88 44.59,56.03 44.59,56.62 44.74,56.77 53.09,56.77
SEMC_D4: length 36
  TOP w0.127: U1.F2 v1(55.17,55.89) ; U20.C8 v2(35.65,54.99)
  BOTTOM w0.102: v1(55.17,55.89) 55.07,55.89 54.89,55.71 53.63,55.71 53.47,55.88
  BOTTOM w0.127: v2(35.65,54.99) 35.24,54.57 35.24,53.78 36.07,52.96 38.35,52.96 38.5,53.11 38.5,53.57 38.65,53.72 38.86,53.72 39.01,53.57 39.01,53.11 39.16,52.96 39.37,52.96 39.51,53.11 39.51,53.57 39.66,53.72 39.87,53.72 40.02,53.57 40.02,53.11 40.17,52.96 40.56,52.96 40.71,53.11 40.71,53.57 40.86,53.72 41.07,53.72 41.22,53.57 41.22,53.11 41.37,52.96 42.04,52.96 42.19,53.11 42.19,53.32 41.83,53.68 41.83,53.89 41.98,54.04 42.19,54.04 42.55,53.68 42.76,53.68 42.91,53.83 42.91,54.04 42.55,54.4 42.55,54.61 42.7,54.76 42.91,54.76 43.27,54.4 43.48,54.4 43.67,54.59 43.67,54.8 43.31,55.16 43.31,55.37 43.46,55.52 43.67,55.52 44.03,55.16 44.24,55.16 44.96,55.88 45.36,55.88 45.5,56.03 45.5,56.24 45.65,56.39 45.86,56.39 46.01,56.24 46.01,56.03 46.16,55.88 46.37,55.88 46.52,56.03 46.52,56.24 46.67,56.39 46.88,56.39 47.03,56.24 47.03,56.03 47.18,55.88 47.39,55.88 47.54,56.03 47.54,56.24 47.68,56.39 47.9,56.39 48.04,56.24 48.04,56.03 48.19,55.88 48.4,55.88 48.55,56.03 48.55,56.24 48.7,56.39 48.91,56.39 49.06,56.24 49.06,56.03 49.21,55.88 49.42,55.88 49.57,56.03 49.57,56.24 49.72,56.39 49.93,56.39 50.08,56.24 50.08,56.03 50.22,55.88 50.44,55.88 50.58,56.03 50.58,56.24 50.73,56.39 50.94,56.39 51.09,56.24 51.09,56.03 51.24,55.88 51.45,55.88 51.6,56.03 51.6,56.24 51.75,56.39 51.96,56.39 52.11,56.24 52.11,56.03 52.26,55.88 53.47,55.88
SEMC_D5: length 35.1
  TOP w0.127: U20.D9 v2(34.85,54.19) ; U1.G5 v1(56.47,55.25)
  BOTTOM w0.102: v1(56.47,55.25) 55.82,55.25 55.61,55.46 53.38,55.46
  BOTTOM w0.127: v2(34.85,54.19) 34.85,53.36 35,53.21 35.28,53.21 35.43,53.06 35.43,52.85 35.28,52.71 35,52.71 34.85,52.56 34.85,52.39 35.05,52.2 35.52,52.2 35.67,52.35 35.67,52.43 35.82,52.58 36.03,52.58 36.18,52.43 36.18,52.35 36.33,52.2 36.54,52.2 36.69,52.35 36.69,52.43 36.84,52.58 37.05,52.58 37.19,52.43 37.19,52.35 37.34,52.2 37.55,52.2 37.7,52.35 37.7,52.43 37.85,52.58 38.06,52.58 38.21,52.43 38.21,52.35 38.36,52.2 38.57,52.2 38.72,52.35 38.72,52.43 38.87,52.58 39.08,52.58 39.23,52.43 39.23,52.35 39.38,52.2 39.59,52.2 39.73,52.35 39.73,52.43 39.88,52.58 40.09,52.58 40.24,52.43 40.24,52.35 40.39,52.2 40.6,52.2 40.75,52.35 40.75,52.43 40.9,52.58 41.11,52.58 41.26,52.43 41.26,52.35 41.41,52.2 41.78,52.2 45.04,55.46 45.32,55.46 45.47,55.31 45.47,55.01 45.62,54.86 45.83,54.86 45.98,55.01 45.98,55.31 46.13,55.46 46.34,55.46 46.48,55.31 46.48,55.01 46.63,54.86 46.84,54.86 46.99,55.01 46.99,55.31 47.14,55.46 47.35,55.46 47.5,55.31 47.5,55.01 47.65,54.86 47.86,54.86 48.01,55.01 48.01,55.31 48.16,55.46 48.37,55.46 48.52,55.31 48.52,55.01 48.67,54.86 48.88,54.86 49.02,55.01 49.02,55.31 49.17,55.46 49.38,55.46 49.53,55.31 49.53,55.01 49.68,54.86 49.89,54.86 50.04,55.01 50.04,55.31 50.19,55.46 50.4,55.46 50.55,55.31 50.55,55.01 50.7,54.86 50.91,54.86 51.06,55.01 51.06,55.31 51.21,55.46 51.42,55.46 51.56,55.31 51.56,55.01 51.71,54.86 51.92,54.86 52.07,55.01 52.07,55.31 52.22,55.46 53.38,55.46
SEMC_D6: length 34.8
  TOP w0.127: U1.H5 v1(56.47,54.6) ; U20.D8 v2(34.85,54.99)
  BOTTOM w0.102: 52.39,54.67 52.83,55.12 53.47,55.12 53.55,55.2 55.38,55.2 55.66,54.92 56.15,54.92 v1(56.47,54.6)
  BOTTOM w0.127: 52.39,54.67 52.27,54.56 44.78,54.56 41.53,51.31 40.35,51.31 40.2,51.46 40.2,51.67 40.05,51.82 39.84,51.82 39.7,51.67 39.7,51.46 39.55,51.31 39.34,51.31 39.19,51.46 39.19,51.67 39.04,51.82 38.83,51.82 38.68,51.67 38.68,51.46 38.53,51.31 38.32,51.31 38.17,51.46 38.17,51.67 38.02,51.82 37.81,51.82 37.66,51.67 37.66,51.46 37.51,51.31 37.3,51.31 37.16,51.46 37.16,51.67 37.01,51.82 36.8,51.82 36.65,51.67 36.65,51.46 36.5,51.31 36.29,51.31 36.14,51.46 36.14,51.67 35.99,51.82 35.78,51.82 35.63,51.67 35.63,51.46 35.48,51.31 35.27,51.31 35.12,51.46 35.12,51.67 34.97,51.82 34.76,51.82 34.62,51.67 34.62,51.46 34.47,51.31 34.04,51.31 33.78,51.56 33.78,52.31 33.93,52.45 34.32,52.45 34.47,52.6 34.47,52.81 34.32,52.96 33.93,52.96 33.78,53.11 33.78,53.32 33.93,53.47 34.32,53.47 34.47,53.62 34.47,54.6 v2(34.85,54.99)
SEMC_D7: length 34.3
  TOP w0.127: U1.H4 v1(55.82,54.6) ; U20.E9 v2(34.05,54.19)
  BOTTOM w0.102: v1(55.82,54.6) 55.63,54.6 55.3,54.92 53.77,54.92 53.59,54.74 52.96,54.74 52.45,54.23
  BOTTOM w0.127: 52.45,54.23 46.23,54.23 45.83,53.83 45.62,53.83 45.32,54.12 45.11,54.12 44.96,53.98 44.96,53.77 45.26,53.47 45.26,53.26 45.11,53.11 44.9,53.11 44.47,53.53 44.26,53.53 44.11,53.38 44.11,53.17 44.54,52.75 44.54,52.54 44.39,52.39 44.18,52.39 43.75,52.81 43.54,52.81 43.39,52.66 43.39,52.45 43.82,52.03 43.82,51.82 43.67,51.67 43.46,51.67 43.03,52.1 42.82,52.1 42.68,51.95 42.68,51.74 43.1,51.31 43.1,51.1 42.93,50.93 33.53,50.93 33.15,51.31 33.15,53.28 v2(34.05,54.19)
SEMC_D8: length 34.6
  TOP w0.127: U1.C6 v1(57.12,58.49) ; U20.E1 v2(34.05,61.38)
  BOTTOM w0.127: v2(34.05,61.38) 33.53,61.91 33.53,62.08 33.68,62.23 33.89,62.23 34.04,62.37 34.04,62.58 33.89,62.73 33.68,62.73 33.53,62.88 33.53,63.09 33.68,63.24 33.89,63.24 34.04,63.39 34.04,63.6 33.89,63.75 33.68,63.75 33.53,63.9 33.53,64.11 33.68,64.26 33.89,64.26 34.04,64.41 34.04,64.62 33.89,64.77 33.68,64.77 33.53,64.91 33.53,65.15 33.78,65.41 51.94,65.41 56.81,60.54 56.81,59.11 57.12,58.8 v1(57.12,58.49)
SEMC_D9: length 35
  TOP w0.127: U1.C5 v1(56.47,58.49) ; U20.D2 v2(34.85,60.58)
  BOTTOM w0.102: v1(56.47,58.49) 56.47,58.67 56.13,59.01 56.13,60.58
  BOTTOM w0.127: v2(34.85,60.58) 34.44,61 34.44,64.29 35.18,65.02 44.97,65.02 45.12,64.88 45.12,64.66 45.26,64.52 45.47,64.52 45.62,64.66 45.62,64.88 45.77,65.02 45.98,65.02 46.13,64.88 46.13,64.66 46.28,64.52 46.49,64.52 46.64,64.66 46.64,64.88 46.79,65.02 47,65.02 47.15,64.88 47.15,64.66 47.3,64.52 47.51,64.52 47.66,64.66 47.66,64.88 47.8,65.02 48.01,65.02 48.16,64.88 48.16,64.66 48.31,64.52 48.52,64.52 48.67,64.66 48.67,64.88 48.82,65.02 49.03,65.02 49.18,64.88 49.18,64.66 49.33,64.52 49.54,64.52 49.69,64.66 49.69,64.88 49.84,65.02 50.05,65.02 50.2,64.88 50.2,64.66 50.34,64.52 50.55,64.52 50.7,64.66 50.7,64.88 50.85,65.02 51.82,65.02 56.13,60.71 56.13,60.58
SEMC_D10: length 34.7
  TOP w0.127: U20.D1 v2(34.85,61.38) ; U1.D5 v1(56.47,57.84)
  BOTTOM w0.102: v1(56.47,57.84) 56.14,58.17 56.14,58.66 55.83,58.98 55.83,60.12
  BOTTOM w0.127: v2(34.85,61.38) 34.85,63.68 35.31,64.14 35.66,64.14 35.81,64.28 35.81,64.49 35.96,64.64 36.17,64.64 36.31,64.49 36.31,64.28 36.46,64.14 36.67,64.14 36.82,64.28 36.82,64.49 36.97,64.64 37.18,64.64 37.33,64.49 37.33,64.28 37.48,64.14 37.69,64.14 37.84,64.28 37.84,64.49 37.99,64.64 38.2,64.64 38.35,64.49 38.35,64.28 38.5,64.14 38.71,64.14 38.85,64.28 38.85,64.49 39,64.64 39.21,64.64 39.36,64.49 39.36,64.28 39.51,64.14 39.72,64.14 39.87,64.28 39.87,64.49 40.02,64.64 40.23,64.64 40.38,64.49 40.38,64.28 40.53,64.14 40.74,64.14 40.89,64.28 40.89,64.49 41.04,64.64 41.25,64.64 41.39,64.49 41.39,64.28 41.54,64.14 41.75,64.14 41.9,64.28 41.9,64.49 42.05,64.64 42.26,64.64 42.41,64.49 42.41,64.28 42.56,64.14 42.77,64.14 42.92,64.28 42.92,64.49 43.07,64.64 43.28,64.64 43.43,64.49 43.43,64.28 43.58,64.14 43.79,64.14 43.93,64.28 43.93,64.49 44.08,64.64 44.29,64.64 44.44,64.49 44.44,64.28 44.59,64.14 51.82,64.14 55.83,60.12
SEMC_D11: length 34.5
  TOP w0.127: U1.C4 v1(55.82,58.49) ; U20.C2 v2(35.65,60.58)
  BOTTOM w0.102: 54.48,60.58 55.55,59.51 55.55,58.93 55.82,58.66 v1(55.82,58.49)
  BOTTOM w0.127: v2(35.65,60.58) 35.24,61 35.24,63.18 35.81,63.75 45.23,63.75 45.38,63.61 45.38,63.14 45.53,62.99 45.74,62.99 45.88,63.14 45.88,63.61 46.03,63.75 46.24,63.75 46.39,63.61 46.39,63.14 46.54,62.99 46.75,62.99 46.9,63.14 46.9,63.61 47.05,63.75 47.26,63.75 47.41,63.61 47.41,63.14 47.56,62.99 47.77,62.99 47.92,63.14 47.92,63.61 48.07,63.75 48.28,63.75 48.42,63.61 48.42,63.14 48.57,62.99 48.78,62.99 48.93,63.14 48.93,63.61 49.08,63.75 49.29,63.75 49.44,63.61 49.44,63.14 49.59,62.99 49.8,62.99 49.95,63.14 49.95,63.61 50.1,63.75 50.31,63.75 50.46,63.61 50.46,63.14 50.61,62.99 50.9,62.99 51.04,63.14 51.04,63.61 51.19,63.75 51.4,63.75 51.55,63.61 51.55,63.14 51.7,62.99 52.07,62.99 54.48,60.58
SEMC_D12: length 35
  TOP w0.127: U20.C1 v2(35.65,61.38) ; U1.D4 v1(55.82,57.84)
  BOTTOM w0.102: v1(55.82,57.84) 55.49,58.17 55.49,58.63 55.24,58.88 55.24,59.05 53.72,60.58
  BOTTOM w0.127: 53.72,60.58 51.69,62.61 45.12,62.61 44.98,62.76 44.98,63.22 44.83,63.37 44.62,63.37 44.47,63.22 44.47,62.76 44.32,62.61 44.11,62.61 43.96,62.76 43.96,63.22 43.81,63.37 43.6,63.37 43.45,63.22 43.45,62.76 43.3,62.61 43.09,62.61 42.94,62.76 42.94,63.22 42.79,63.37 42.58,63.37 42.44,63.22 42.44,62.76 42.29,62.61 42.08,62.61 41.93,62.76 41.93,63.22 41.78,63.37 41.57,63.37 41.42,63.22 41.42,62.76 41.27,62.61 41.06,62.61 40.91,62.76 40.91,63.22 40.76,63.37 40.55,63.37 40.4,63.22 40.4,62.76 40.25,62.61 40.04,62.61 39.9,62.76 39.9,63.22 39.75,63.37 39.54,63.37 39.39,63.22 39.39,62.76 39.24,62.61 39.03,62.61 38.88,62.76 38.88,63.22 38.73,63.37 38.52,63.37 38.37,63.22 38.37,62.76 38.22,62.61 38.01,62.61 37.86,62.76 37.86,63.22 37.71,63.37 37.5,63.37 37.36,63.22 37.36,62.76 37.21,62.61 36.96,62.61 36.81,62.76 36.81,63.1 36.67,63.25 36.46,63.25 36.31,63.1 36.31,62.76 36.16,62.61 35.81,62.61 35.65,62.45 v2(35.65,61.38)
SEMC_D13: length 34.4
  TOP w0.127: U1.E5 v1(56.47,57.19) ; U20.B2 v2(36.45,60.58)
  BOTTOM w0.102: 52.45,59.82 53.59,58.67 54.51,58.67 55.66,57.52 56.14,57.52 v1(56.47,57.19)
  BOTTOM w0.127: v2(36.45,60.58) 36.87,61 37.56,61 37.85,60.71 38.09,60.71 38.24,60.85 38.24,61.7 38.39,61.85 38.6,61.85 38.75,61.7 38.75,60.85 38.9,60.71 39.11,60.71 39.26,60.85 39.26,61.7 39.4,61.85 39.61,61.85 39.76,61.7 39.76,60.85 39.91,60.71 40.12,60.71 40.27,60.85 40.27,61.7 40.42,61.85 40.63,61.85 40.78,61.7 40.78,60.85 40.93,60.71 41.14,60.71 41.29,60.85 41.29,61.7 41.44,61.85 41.65,61.85 41.8,61.7 41.8,60.85 41.94,60.71 42.15,60.71 42.3,60.85 42.3,61.7 42.45,61.85 42.66,61.85 42.81,61.7 42.81,60.85 42.96,60.71 43.17,60.71 43.32,60.85 43.32,61.7 43.47,61.85 43.68,61.85 43.83,61.7 43.83,60.85 43.98,60.71 51.56,60.71 52.45,59.82
SEMC_D14: length 34.7
  TOP w0.127: U20.B1 v2(36.45,61.38) ; U1.C3 v1(55.17,58.49)
  BOTTOM w0.102: 52.83,60.2 53.99,59.04 54.63,59.04 v1(55.17,58.49)
  BOTTOM w0.127: 52.83,60.2 51.94,61.09 51.63,61.09 51.48,61.24 51.48,61.57 51.33,61.72 51.12,61.72 50.97,61.57 50.97,61.24 50.82,61.09 50.59,61.09 50.44,61.24 50.44,62.08 50.29,62.23 50.08,62.23 49.93,62.08 49.93,61.24 49.78,61.09 49.49,61.09 49.34,61.24 49.34,62.08 49.19,62.23 48.98,62.23 48.83,62.08 48.83,61.24 48.68,61.09 48.47,61.09 48.32,61.24 48.32,62.08 48.17,62.23 47.96,62.23 47.81,62.08 47.81,61.24 47.67,61.09 47.46,61.09 47.31,61.24 47.31,62.08 47.16,62.23 46.95,62.23 46.8,62.08 46.8,61.24 46.65,61.09 46.44,61.09 46.29,61.24 46.29,62.08 46.14,62.23 45.93,62.23 45.78,62.08 45.78,61.24 45.63,61.09 45.42,61.09 45.27,61.24 45.27,62.08 45.13,62.23 44.92,62.23 44.77,62.08 44.77,61.24 44.62,61.09 44.41,61.09 44.26,61.24 44.26,62.08 44.11,62.23 37.3,62.23 v2(36.45,61.38)
SEMC_D15: length 34.3
  TOP w0.127: U1.E4 v1(55.82,57.19) ; U20.A2 v2(37.25,60.58)
  BOTTOM w0.102: v1(55.82,57.19) 55.63,57.19 55.3,57.52 55.01,57.52 54.24,58.29 52.83,58.29 52.32,58.8
  BOTTOM w0.127: v2(37.25,60.58) 37.51,60.33 44.31,60.33 44.46,60.18 44.46,59.33 44.61,59.18 44.82,59.18 44.97,59.33 44.97,60.18 45.12,60.33 45.33,60.33 45.48,60.18 45.48,59.33 45.62,59.18 45.83,59.18 45.98,59.33 45.98,60.18 46.13,60.33 46.34,60.33 46.49,60.18 46.49,59.33 46.64,59.18 46.85,59.18 47,59.33 47,60.18 47.15,60.33 47.36,60.33 47.51,60.18 47.51,59.33 47.66,59.18 47.87,59.18 48.02,59.33 48.02,60.18 48.16,60.33 48.37,60.33 48.52,60.18 48.52,59.33 48.67,59.18 48.88,59.18 49.03,59.33 49.03,60.18 49.18,60.33 49.39,60.33 49.54,60.18 49.54,59.33 49.69,59.18 49.95,59.18 50.1,59.33 50.1,60.18 50.25,60.33 50.46,60.33 50.61,60.18 50.61,59.33 50.75,59.18 51,59.18 51.15,59.33 51.15,59.8 51.3,59.94 51.69,59.94 52.32,59.31 52.32,58.8
SEMC_DM0: length 34.5
  TOP w0.127: U1.H3 v1(55.17,54.6) ; U20.E8 v2(34.05,54.99)
  BOTTOM w0.102: 52.45,53.85 52.96,54.36 53.59,54.36 53.83,54.6 v1(55.17,54.6)
  BOTTOM w0.127: 52.45,53.85 47.5,53.85 47.11,53.46 46.9,53.46 46.67,53.7 46.46,53.7 46.31,53.55 46.31,53.34 46.54,53.1 46.54,52.89 46.35,52.7 46.14,52.7 45.78,53.06 45.57,53.06 45.42,52.91 45.42,52.7 45.78,52.34 45.78,52.13 45.63,51.98 45.42,51.98 45.06,52.34 44.85,52.34 44.7,52.19 44.7,51.98 45.06,51.62 45.06,51.41 44.91,51.26 44.7,51.26 44.34,51.62 44.13,51.62 43.98,51.47 43.98,51.26 44.34,50.9 44.34,50.69 44.2,50.55 33.27,50.55 32.77,51.05 32.77,53.7 v2(34.05,54.99)
SEMC_DM1: length 34.4
  TOP w0.127: U1.D6 v1(57.12,57.84) ; U20.F1 v2(33.25,61.38)
  BOTTOM w0.102: v1(57.12,57.84) 57.12,58.01 57.44,58.33 57.44,58.78 57.15,59.08 57.15,60.58
  BOTTOM w0.127: v2(33.25,61.38) 33.15,61.49 33.15,65.28 33.66,65.79 52.07,65.79 57.15,60.71 57.15,60.58
SEMC_DQS: length 7
  TOP w0.127: C76.1 60.33,64.39 57.78,61.84 57.78,59.14 U1.B7
SEMC_RAS: length 34.3
  TOP w0.127: U20.F8 32.49,55.02 32.49,53.77 32.77,53.49 32.77,52.83 33.91,51.69 40.26,51.69 40.42,51.85 40.63,51.85 40.8,51.68 41.01,51.68 41.16,51.83 41.16,52.04 40.99,52.21 40.99,52.42 41.12,52.55 41.33,52.55 41.57,52.32 41.78,52.32 41.93,52.47 41.93,52.68 41.69,52.91 41.69,53.12 41.84,53.27 42.05,53.27 42.29,53.04 42.5,53.04 42.65,53.19 42.65,53.4 42.41,53.63 42.41,53.84 42.56,53.99 42.77,53.99 43,53.76 43.21,53.76 43.36,53.9 43.36,54.12 43.13,54.35 43.13,54.56 43.28,54.71 43.49,54.71 43.72,54.47 43.93,54.47 44.08,54.62 44.08,54.83 43.85,55.07 43.85,55.28 44,55.43 44.21,55.43 44.51,55.13 44.72,55.13 44.86,55.28 44.86,55.49 44.57,55.79 44.57,56 44.72,56.15 44.93,56.15 45.22,55.85 45.43,55.85 45.58,56 45.58,56.21 45.29,56.51 45.29,56.72 45.47,56.9 53.59,56.9 53.9,57.2 54.53,57.2 U1.D2
SEMC_WE: length 35.3
  TOP w0.127: U20.F9 32.85,53.89 33.15,53.59 33.15,53.09 34.16,52.07 34.9,52.07 35.04,52.22 35.04,52.68 35.19,52.83 35.4,52.83 35.55,52.68 35.55,52.22 35.7,52.07 35.91,52.07 36.06,52.22 36.06,52.68 36.21,52.83 36.42,52.83 36.57,52.68 36.57,52.22 36.72,52.07 36.93,52.07 37.08,52.22 37.08,52.68 37.22,52.83 37.44,52.83 37.58,52.68 37.58,52.22 37.73,52.07 37.94,52.07 38.09,52.22 38.09,52.68 38.24,52.83 38.45,52.83 38.6,52.68 38.6,52.22 38.75,52.07 38.96,52.07 39.11,52.22 39.11,52.68 39.26,52.83 39.47,52.83 39.62,52.68 39.62,52.22 39.76,52.07 39.99,52.07 40.14,52.22 40.14,52.97 40.76,53.58 40.97,53.58 41.14,53.41 41.35,53.41 41.49,53.56 41.49,53.77 41.32,53.94 41.32,54.15 41.47,54.3 41.68,54.3 41.85,54.13 42.06,54.13 42.21,54.28 42.21,54.49 42.04,54.66 42.04,54.87 42.19,55.02 42.4,55.02 42.57,54.85 42.78,54.85 42.93,55 42.93,55.21 42.76,55.38 42.76,55.59 42.91,55.74 43.12,55.74 43.29,55.57 43.5,55.57 43.65,55.72 43.65,55.93 43.48,56.1 43.48,56.31 43.63,56.46 43.84,56.46 44.01,56.29 44.22,56.29 44.37,56.44 44.37,56.65 44.2,56.82 44.2,57.03 44.45,57.28 53.34,57.28 53.58,57.52 U1.D1
SENSOR_3V3: length 29.2
  TOP w0.254: 61.46,79.63 U32.14 ; 58.8,78.47 U32.1
  TOP w0.305: R265.1 67.94,77.6 68.08,77.73 R262.1 68.58,77.73 69.84,76.47 R261.1 v2(69.84,74.8) ; R271.1 v2(58.55,72.64) ; 58.8,78.47 58.02,79.25 C188.1 ; C187.1 61.46,79.63
  TOP w0.381: R268.1 v2(60.96,69.98)
  BOTTOM w0.381: v2(60.96,69.98) 58.55,72.39 v2(58.55,72.64) 58.55,73.28 60.07,74.8 v2(69.84,74.8)
SPDIF_BUF: length 5.8
  TOP w0.381: R122.1 R124.2 123.83,48.55 124.21,48.93 124.21,50.4 123.83,50.78 U15.4
SPDIF_COAX_OUT: length 5.8
  TOP w0.508: T2.1 135.27,43.32 137.17,45.22 J18.2
SPDIF_GND_PRI: length 4.6
  TOP w0.381: R125.1 R123.2 128.14,48.4 T2.4
SPDIF_OUT_PRI: length 4.5
  TOP w0.381: C139.2 R123.1 128.14,43.32 T2.6
SPDIF_VCC: length 18.1
  TOP w0.254: 121.54,58.29 122.3,57.53 C133.1 U14.5
  TOP w0.381: 121.54,58.29 121.28,58.55 117.98,58.55 J13.1 119.89,53.84 C138.1 U15.1 U15.5
SPK_LN: length 13.2
  TOP w0.254: U13.23 128.89,22.07 129.36,21.59 v2(130.56,21.59) ; R119.1 v2(140.46,22.23)
  BOTTOM w0.254: v2(140.46,22.23) 139.83,21.59 v2(130.56,21.59)
SPK_LP: length 7.2
  TOP w0.254: v2(130.81,22.86) 130.52,23.15 U13.25 ; R121.1 v2(136.14,22.23)
  BOTTOM w0.254: v2(136.14,22.23) 131.44,22.23 v2(130.81,22.86)
SPK_RN: length 24.5
  TOP w0.254: v2(127.25,21.59) 126.88,21.96 U13.19 ; R118.1 147.32,22.35 146.69,22.99 v2(143,22.99)
  BOTTOM w0.254: v2(127.25,21.59) 127.89,22.23 129.03,22.23 131.06,20.19 140.21,20.19 v2(143,22.99)
SPK_RP: length 18
  TOP w0.254: v2(128.6,21.59) 128.39,21.8 U13.22 ; R120.1 v2(143,22.23)
  BOTTOM w0.254: v2(143,22.23) 140.41,19.63 130.56,19.63 v2(128.6,21.59)
SW1_RST_B: length 18.3
  TOP w0.127: SW9.4 SW9.3 128.55,92.05 129.28,91.32 C272.1 134.24,90.81 J43.2
SWD_CLK_TGTMCU_BUF: length 9.6
  TOP w0.127: J48.1 103,98.17 96.27,98.17 R416.2
SWD_DIO_TGTMCU_BUF: length 5.6
  TOP w0.127: U46.4 111.87,94.5 111.51,94.86 R419.1 v2(110.62,95.63)
  BOTTOM w0.127: J47.1 109.22,95.63 v2(110.62,95.63)
TC_SDA_USB_ID: length 18.4
  TOP w0.127: U38.F1 132.18,69.6 136.02,69.6 136.73,70.31 139.14,70.31 140.46,71.63 140.46,73.66 140.97,74.17 144.4,74.17 145.03,73.53 145.86,73.53 J41.4
TCK_SWCLK: length 45.9
  TOP w0.127: U48.2 95.76,90.42 96.24,89.94 110.08,89.94 111.25,88.77 122.79,88.77 125.9,85.67 128.82,85.67 132.81,81.67 U38.H10
TDO_SWO: length 48.2
  TOP w0.127: U38.J8 133.22,76.56 133.22,77.22 133.06,77.37 132.65,77.37 132.42,77.6 132.42,81.53 128.66,85.29 125.74,85.29 122.56,88.47 94.09,88.47 93.97,88.6 U49.3
TMS_SWDIO: length 45.9
  TOP w0.127: U38.K4 134.94,72.97 136.27,74.29 136.27,80.52 129.55,87.24 126.37,87.24 123.45,90.16 113.67,90.16 113.33,90.5 111.18,90.5 109.98,91.69 109.98,95.89 110.56,96.46 U46.3
TMS_SWDIO_TXEN: length 41.8
  TOP w0.127: U46.5 R414.1 v2(111.63,92.71) ; U38.J4 134,73.36 134.83,73.36 135.86,74.4 135.86,80.24 129.29,86.81 126.37,86.81 123.34,89.84 112.45,89.84 v2(112.27,90.02)
  BOTTOM w0.127: v2(112.27,90.02) 112.27,92.08 v2(111.63,92.71)
TP_2102_A: length 1.8
  TOP w0.127: TP29.1 143.26,90.3 U44.3
TP_2102_B: length 2.2
  TOP w0.127: TP30.1 142.62,87.76 142.86,87.99 U44.6
UART1_RX_TGTMCU_BUF: length 4.8
  TOP w0.127: U45.8 117.94,93.81 J45.1
UART1_RXD: length 93.8
  TOP w0.127: J45.2 120.9,92.46 v2(119.63,91.19) R411.2 ; U1.L14 62.87,52.97 62.99,52.84 74.59,52.84 76.61,50.83 78.45,50.83 78.74,50.53 79.52,50.53 80.64,51.65 103.27,51.65 108.85,57.24 108.85,82.31 113.54,87 114.55,87 v2(114.68,86.87)
  BOTTOM w0.127: v2(119.63,91.19) 119,91.19 v2(114.68,86.87)
UART1_TX_TGTMCU_BUF: length 7.9
  TOP w0.127: U45.1 117.94,98 118.24,98.3 123.06,98.3 J46.1
UART1_TXD: length 97.7
  TOP w0.127: v2(115.44,86.87) 114.94,87.38 113.38,87.38 108.47,82.47 108.47,57.29 103.14,51.96 80.43,51.96 79.32,50.84 78.93,50.84 78.63,51.13 76.73,51.13 74.71,53.15 63.12,53.15 U1.K14 ; J46.2 R393.2 120.9,91.69 v2(120.4,91.19)
  BOTTOM w0.127: v2(120.4,91.19) 119.76,90.55 119.13,90.55 v2(115.44,86.87)
UART_RXD_ISP: length 30.5
  TOP w0.127: v2(114.17,87.88) 114.45,88.16 122.4,88.16 125.6,84.96 128.52,84.96 132.01,81.48 U38.G10 ; U45.5 115.99,92.5 v2(114.81,91.31)
  BOTTOM w0.127: v2(114.17,87.88) 114.17,90.68 v2(114.81,91.31)
UART_TXD_ISP: length 50
  TOP w0.127: U38.G7 132.4,75.76 134.8,75.76 135.38,76.34 135.38,80.18 129.13,86.43 126.21,86.43 123.11,89.53 111.63,89.53 109.6,91.57 109.6,96.14 111.38,97.92 114.17,97.92 114.56,97.53 U45.4
USER_BUTTON: length 96.2
  TOP w0.127: SW8.4 SW8.3 32.17,68.87 27.05,63.75 27.05,57.02 27.69,56.39 27.69,46.99 28.92,45.76 30.26,45.76 v2(30.73,46.23) ; v2(45.97,36.45) 46.48,35.94 57.53,35.94 59.05,37.47 TP6.1 59.82,39.12 v2(59.82,39.24)
  TOP w0.254: U1.L6 v1(57.12,52.65)
  BOTTOM w0.102: 57.3,49.91 57.3,50.09 57.2,50.19 57.2,52.32 57.12,52.4 v1(57.12,52.65)
  BOTTOM w0.127: v2(45.97,36.45) 44.96,36.45 37.72,43.69 33.91,43.69 31.37,46.23 v2(30.73,46.23) ; v2(59.82,39.24) 59.82,40.77 58.17,42.42 58.17,42.95 56.77,44.35 56.77,48.34 57.3,48.87 57.3,49.91
